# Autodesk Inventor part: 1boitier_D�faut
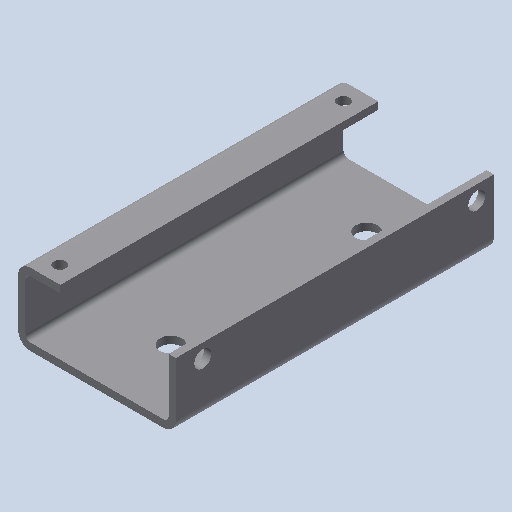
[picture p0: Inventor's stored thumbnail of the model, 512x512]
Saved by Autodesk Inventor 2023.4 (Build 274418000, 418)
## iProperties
Created: 2011-01
Part Number: 1boitier_D�faut
Document SubType Name: Modeling
Designer: eric
Density: 1 g/cm^3
Mass: 48.0197 g
Surface Area: 339.389 cm^2
Volume: 48.0197 cm^3
Material: Générique
Appearance: Par défaut
Author: eric
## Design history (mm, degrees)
feature "Base1"
node "Corps solides"
node "Corps surfaciques"
node "Solide1"
